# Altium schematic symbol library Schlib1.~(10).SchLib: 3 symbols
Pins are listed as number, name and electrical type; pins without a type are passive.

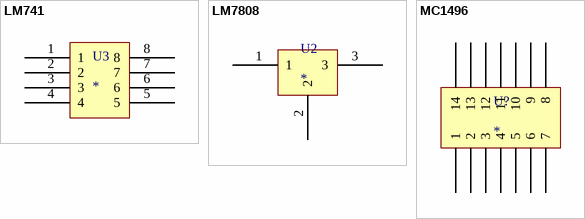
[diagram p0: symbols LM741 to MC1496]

## LM741
designator U3
pins: 1, 2, 3, 4, 5, 6, 7, 8

## LM7808
designator U2
pins: 1, 2, 3

## MC1496
designator U?
pins: 1, 2, 3, 4, 5, 6, 7, 8, 9, 10, 11, 12, 13, 14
